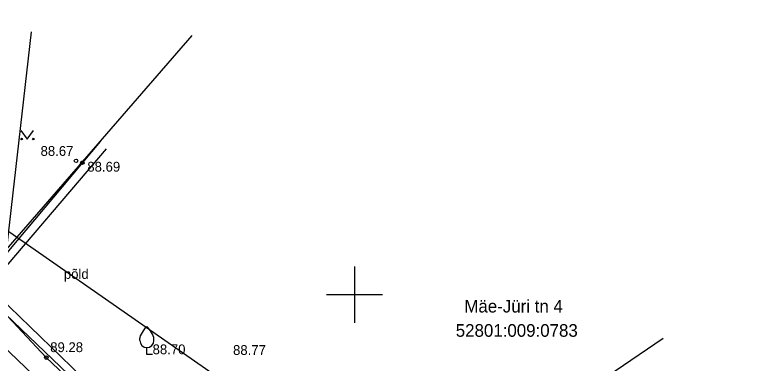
# Model space of a CAD drawing. Extents: x 648748 to 649126, y 6457789 to 6458252.
# Drawn here: x 649025.8 to 649079.4, y 6457995.1 to 6458019.9 of the extents above; entities that cross this region are included whole.
import ezdxf

# ---------------------------------------------------------------- set-up
doc = ezdxf.new("R2010")
doc.units = 0
for name, color, linetype in [('AED', 7, 'Continuous'), ('HALJASTUS', 7, 'Continuous'), ('HOONE', 7, 'Continuous'), ('KORGUS-EH2000', 7, 'Continuous'), ('MPOHULIIN', 7, 'Continuous'), ('PIIR', 7, 'Continuous'), ('PUU', 7, 'Continuous'), ('TEE', 7, 'Continuous'), ('VORK', 7, 'Continuous'), ('VTRASS', 7, 'Continuous')]:
    doc.layers.add(name, color=color, linetype=linetype)

msp = doc.modelspace()

# ---------------------------------------------------------------- linework, layer by layer
at = {"layer": 'AED'}
msp.add_lwpolyline([(649031.864, 6458010.925), (649023.216, 6458000.624), (649028.027, 6457995.514), (649035.951, 6457988.021), (649039.394, 6457984.81)], dxfattribs=at)
at = {"layer": 'HALJASTUS'}
for p, q in [((649026.207, 6458011.696), (649026.67, 6458011.09)), ((649026.67, 6458011.09), (649027.116, 6458011.696))]:
    msp.add_line(p, q, dxfattribs=at)
for centre in [(649026.269, 6458011.09), (649027.098, 6458011.09)]:
    msp.add_circle(centre, 0.055, dxfattribs=at)
at = {"layer": 'HOONE'}
msp.add_lwpolyline([(649072.015, 6457996.882), (649063.446, 6457991.053), (649068.243, 6457984.001), (649073.604, 6457987.648), (649075.908, 6457984.326), (649079.415, 6457986.758), (649077.261, 6457989.865)], dxfattribs=at)
at = {"layer": 'KORGUS-EH2000'}
for centre in [(649030.15, 6458009.534), (649030.601, 6458009.401), (649028.027, 6457995.514)]:
    msp.add_circle(centre, 0.125, dxfattribs=at)
at = {"layer": 'MPOHULIIN'}
msp.add_line((649045.712, 6457990.322), (649008.42, 6458016.198), dxfattribs=at)
at = {"layer": 'PIIR'}
for p, q in [((649022.96, 6458000.66), (649038.421, 6458018.473)), ((649065.03, 6457960.54), (649022.96, 6458000.66))]:
    msp.add_line(p, q, dxfattribs=at)
at = {"layer": 'PUU'}
for p, q in [((649035.201, 6457995.73), (649035.201, 6457996.23)), ((649035.601, 6457995.73), (649035.201, 6457995.73))]:
    msp.add_line(p, q, dxfattribs=at)
for points in [[(649039.41, 6457985.592), (649023.916, 6458000.565), (649032.315, 6458010.397)], [(649034.701, 6457996.73), (649034.701, 6457996.88), (649034.711, 6457996.945), (649034.746, 6457997.075), (649034.806, 6457997.195), (649034.951, 6457997.43), (649035.111, 6457997.635), (649035.201, 6457997.73)], [(649035.701, 6457996.73), (649035.701, 6457996.88), (649035.691, 6457996.945), (649035.656, 6457997.075), (649035.596, 6457997.195), (649035.451, 6457997.43), (649035.291, 6457997.635), (649035.201, 6457997.73)]]:
    msp.add_lwpolyline(points, dxfattribs=at)
msp.add_arc((649035.201, 6457996.73), 0.5, 180, 0, dxfattribs=at)
at = {"layer": 'TEE'}
msp.add_lwpolyline([(649073.892, 6457980.444), (649075.277, 6457978.898), (649074.998, 6457977.546), (649073.91, 6457975.39), (649075.219, 6457973.916), (649077.682, 6457970.841), (649078.634, 6457968.92), (649078.21, 6457966.199), (649076.118, 6457962.885), (649072.987, 6457959.848), (649068.76, 6457959.373), (649065.353, 6457959.385), (649062.208, 6457961.227), (649055.218, 6457967.101), (649039.374, 6457982.53), (649021.477, 6457999.638), (649003.487, 6458020.927), (649002.852, 6458022.042), (649010.237, 6458028.696), (649016.817, 6458021.893)], dxfattribs=at)
at = {"layer": 'VORK'}
for p, q in [((649050, 6458002), (649050, 6457998)), ((649048, 6458000), (649052, 6458000))]:
    msp.add_line(p, q, dxfattribs=at)
at = {"layer": 'VTRASS'}
msp.add_lwpolyline([(649026.951, 6458018.739), (649024.71, 6457999.32), (649021.448, 6457994.005), (649059.981, 6457955.664), (649063.472, 6457950.371), (649064.082, 6457948.494), (649063.446, 6457947.594)], dxfattribs=at)

# ---------------------------------------------------------------- texts
at = {"layer": 'HALJASTUS'}
msp.add_text('põld', height=0.7, dxfattribs=at).set_placement((649029.28, 6458001.125))
at = {"layer": 'KORGUS-EH2000'}
for s, p in [('88.67', (649027.62, 6458009.89)), ('88.69', (649030.954, 6458008.766)), ('89.28', (649028.307, 6457995.906)), ('88.70', (649035.608, 6457995.753)), ('88.77', (649041.344, 6457995.703))]:
    msp.add_text(s, height=0.7, dxfattribs=at).set_placement(p)
at = {"layer": 'PIIR'}
for s, p in [('Mäe-Jüri tn 4', (649057.838, 6457998.728)), ('52801:009:0783', (649057.225, 6457996.999))]:
    msp.add_text(s, height=0.9, dxfattribs=at).set_placement(p)

doc.saveas('drawing.dxf')
